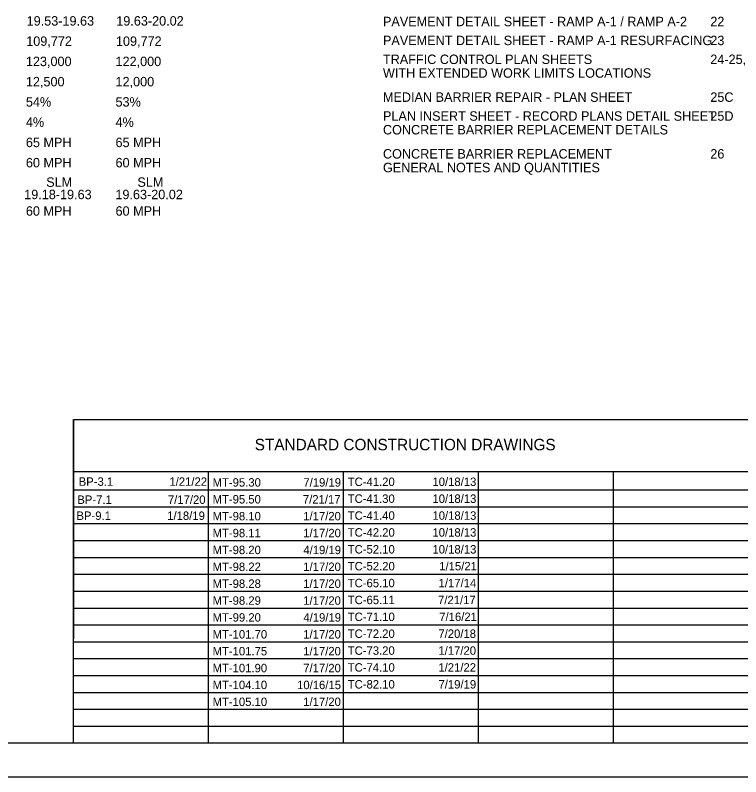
# Model space of a CAD drawing. Extents: x -17.5 to 72.9, y -57.8 to 32.3.
# Drawn here: x 8.89 to 19.64, y 0 to 11.28 of the extents above; entities that cross this region are included whole.
import ezdxf

# ---------------------------------------------------------------- set-up
doc = ezdxf.new("R2010")
doc.units = 0
for name, color, linetype in [('SH_Border', 7, 'Continuous'), ('SH_Cut_Line', 7, 'Continuous'), ('SH_Data', 7, 'Continuous'), ('SH_Text', 7, 'Continuous')]:
    doc.layers.add(name, color=color, linetype=linetype)

msp = doc.modelspace()

# ---------------------------------------------------------------- linework, layer by layer
at = {"layer": 'SH_Border'}
msp.add_lwpolyline([(1.5, 21.5), (33.5, 21.5), (33.5, 0.5), (1.5, 0.5)], close=True, dxfattribs=at)
at = {"layer": 'SH_Cut_Line'}
msp.add_lwpolyline([(0, 0), (34, 0), (34, 22), (0, 22)], close=True, dxfattribs=at)
at = {"layer": 'SH_Data'}
for p, q in [((9.75, 5.292), (23.2, 5.292)), ((9.75, 0.5), (9.75, 5.292)), ((9.75, 5.292), (9.75, 2.042)), ((9.75, 4.521), (23.2, 4.521)), ((11.75, 0.5), (11.75, 4.521)), ((13.75, 0.5), (13.75, 4.521)), ((15.75, 0.5), (15.75, 4.521)), ((17.75, 0.5), (17.75, 4.521)), ((9.75, 4.25), (23.2, 4.25)), ((9.75, 4), (23.2, 4)), ((9.75, 3.75), (23.2, 3.75)), ((9.75, 3.5), (23.2, 3.5)), ((9.75, 3.25), (23.2, 3.25)), ((9.75, 3), (23.2, 3)), ((9.75, 2.75), (23.2, 2.75)), ((9.75, 2.5), (23.2, 2.5)), ((9.75, 2.25), (23.2, 2.25)), ((9.75, 2), (23.2, 2)), ((9.75, 1.75), (23.2, 1.75)), ((9.75, 1.5), (23.2, 1.5)), ((9.75, 1.25), (23.2, 1.25)), ((9.75, 1), (23.2, 1)), ((9.75, 0.75), (23.2, 0.75))]:
    msp.add_line(p, q, dxfattribs=at)

# ---------------------------------------------------------------- texts
for s, p in [('19.53-19.63', (9.055, 11.127)), ('19.63-20.02', (10.383, 11.127)), ('PAVEMENT DETAIL SHEET - RAMP A-1 / RAMP A-2', (14.334, 11.118)), ('22', (19.184, 11.118)), ('109,772', (9.049, 10.827)), ('109,772', (10.378, 10.827)), ('PAVEMENT DETAIL SHEET - RAMP A-1 RESURFACING', (14.334, 10.838)), ('23', (19.184, 10.838)), ('123,000', (9.044, 10.527)), ('122,000', (10.372, 10.527)), ('TRAFFIC CONTROL PLAN SHEETS', (14.334, 10.558)), ('24-25, 25A, 25B', (19.184, 10.558)), ('WITH EXTENDED WORK LIMITS LOCATIONS', (14.334, 10.355)), ('12,500', (9.044, 10.227)), ('12,000', (10.372, 10.227)), ('54%', (9.044, 9.927)), ('53%', (10.372, 9.927)), ('MEDIAN BARRIER REPAIR - PLAN SHEET', (14.334, 9.998)), ('25C', (19.184, 9.998)), ('PLAN INSERT SHEET - RECORD PLANS DETAIL SHEET', (14.334, 9.718)), ('25D', (19.184, 9.718)), ('4%', (9.044, 9.627)), ('4%', (10.372, 9.627)), ('CONCRETE BARRIER REPLACEMENT DETAILS', (14.334, 9.515)), ('65 MPH', (9.044, 9.327)), ('65 MPH', (10.372, 9.327)), ('CONCRETE BARRIER REPLACEMENT', (14.334, 9.158)), ('26', (19.184, 9.158)), ('60 MPH', (9.044, 9.027)), ('60 MPH', (10.372, 9.027)), ('GENERAL NOTES AND QUANTITIES', (14.334, 8.955)), ('SLM', (9.345, 8.739)), ('SLM', (10.696, 8.739)), ('19.18-19.63', (9.019, 8.556)), ('19.63-20.02', (10.37, 8.556)), ('60 MPH', (9.044, 8.311)), ('60 MPH', (10.372, 8.311))]:
    msp.add_text(s, height=0.14, dxfattribs=at).set_placement(p)
at = {"layer": 'SH_Text'}
for s, height, p in [('STANDARD CONSTRUCTION DRAWINGS', 0.17, (12.434, 4.836)), ('BP-3.1', 0.125, (9.826, 4.31)), ('1/21/22', 0.125, (11.17, 4.31)), ('MT-95.30', 0.125, (11.81, 4.298)), ('7/19/19', 0.125, (13.155, 4.298)), ('TC-41.20', 0.125, (13.812, 4.307)), ('10/18/13', 0.125, (15.067, 4.307)), ('MT-95.50', 0.125, (11.81, 4.048)), ('7/21/17', 0.125, (13.148, 4.048)), ('TC-41.30', 0.125, (13.812, 4.057)), ('10/18/13', 0.125, (15.067, 4.057)), ('BP-7.1', 0.125, (9.806, 4.042)), ('7/17/20', 0.125, (11.148, 4.042)), ('BP-9.1', 0.125, (9.793, 3.805)), ('1/18/19', 0.125, (11.138, 3.805)), ('MT-98.10', 0.125, (11.81, 3.798)), ('1/17/20', 0.125, (13.153, 3.798)), ('TC-41.40', 0.125, (13.812, 3.807)), ('10/18/13', 0.125, (15.067, 3.807)), ('MT-98.11', 0.125, (11.81, 3.548)), ('1/17/20', 0.125, (13.153, 3.548)), ('TC-42.20', 0.125, (13.812, 3.557)), ('10/18/13', 0.125, (15.067, 3.557)), ('MT-98.20', 0.125, (11.81, 3.298)), ('4/19/19', 0.125, (13.155, 3.298)), ('TC-52.10', 0.125, (13.812, 3.307)), ('10/18/13', 0.125, (15.067, 3.307)), ('MT-98.22', 0.125, (11.81, 3.048)), ('1/17/20', 0.125, (13.153, 3.048)), ('TC-52.20', 0.125, (13.812, 3.057)), ('1/15/21', 0.125, (15.168, 3.057)), ('TC-65.10', 0.125, (13.812, 2.807)), ('1/17/14', 0.125, (15.158, 2.807)), ('MT-98.28', 0.125, (11.81, 2.798)), ('1/17/20', 0.125, (13.153, 2.798)), ('MT-98.29', 0.125, (11.81, 2.548)), ('1/17/20', 0.125, (13.153, 2.548)), ('TC-65.11', 0.125, (13.812, 2.557)), ('7/21/17', 0.125, (15.15, 2.557)), ('MT-99.20', 0.125, (11.81, 2.298)), ('4/19/19', 0.125, (13.155, 2.298)), ('TC-71.10', 0.125, (13.812, 2.307)), ('7/16/21', 0.125, (15.168, 2.307)), ('MT-101.70', 0.125, (11.81, 2.048)), ('1/17/20', 0.125, (13.153, 2.048)), ('TC-72.20', 0.125, (13.812, 2.057)), ('7/20/18', 0.125, (15.155, 2.057)), ('MT-101.75', 0.125, (11.81, 1.798)), ('1/17/20', 0.125, (13.153, 1.798)), ('TC-73.20', 0.125, (13.812, 1.807)), ('1/17/20', 0.125, (15.155, 1.807)), ('MT-101.90', 0.125, (11.81, 1.548)), ('7/17/20', 0.125, (13.153, 1.548)), ('TC-74.10', 0.125, (13.812, 1.557)), ('1/21/22', 0.125, (15.155, 1.557)), ('MT-104.10', 0.125, (11.81, 1.298)), ('10/16/15', 0.125, (13.062, 1.298)), ('TC-82.10', 0.125, (13.812, 1.307)), ('7/19/19', 0.125, (15.157, 1.307)), ('MT-105.10', 0.125, (11.81, 1.048)), ('1/17/20', 0.125, (13.153, 1.048))]:
    msp.add_text(s, height=height, dxfattribs=at).set_placement(p)

doc.saveas('drawing.dxf')
